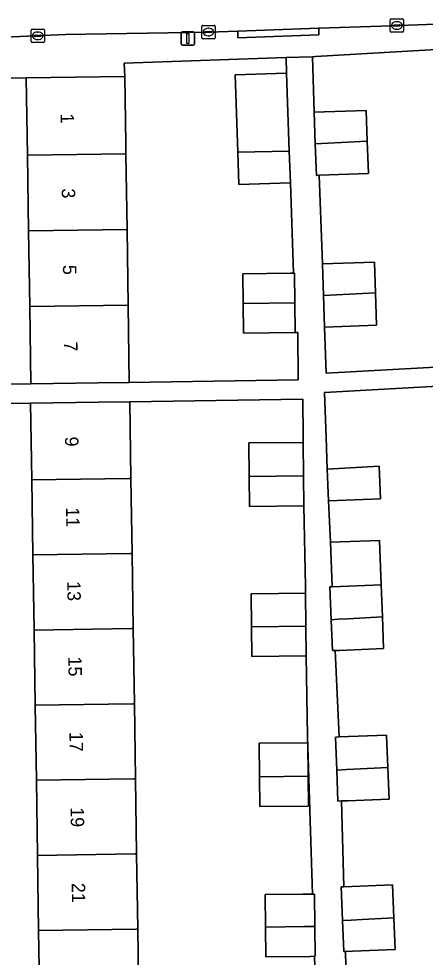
# Model space of a CAD drawing. Extents: x 162250 to 162661, y 380743 to 381606.
# Drawn here: x 162441.5 to 162471.8, y 380821.9 to 380891.8 of the extents above; entities that cross this region are included whole.
import ezdxf

# ---------------------------------------------------------------- set-up
doc = ezdxf.new("R2010")
doc.units = 0
for name, color, linetype in [('IMGEO_Erf', 7, 'Continuous'), ('IMGEO_Kolk', 7, 'Continuous'), ('IMGEO_Lichtmast', 7, 'Continuous'), ('IMGEO_Pand', 7, 'Continuous'), ('IMGEO_Pand_nummerreeks', 7, 'Continuous'), ('IMGEO_Rijbaan_lokaal_open', 7, 'Continuous'), ('IMGEO_Voetpad_open', 7, 'Continuous')]:
    doc.layers.add(name, color=color, linetype=linetype)

msp = doc.modelspace()

# ---------------------------------------------------------------- linework, layer by layer
at = {"layer": 'IMGEO_Erf'}
for points in [[(162476.003, 380877.506), (162472.856, 380877.338), (162472.553, 380882.993), (162475.699, 380883.161), (162475.657, 380883.948), (162475.388, 380888.933), (162475.802, 380888.955), (162475.764, 380889.728), (162473.498, 380889.596), (162463.611, 380889.016), (162463.383, 380889.008), (162463.524, 380884.867), (162467.402, 380885), (162467.48, 380882.72), (162467.564, 380880.294), (162463.905, 380880.169), (162464.132, 380873.557), (162468.01, 380873.69), (162468.088, 380871.41), (162468.172, 380868.984), (162464.294, 380868.851), (162464.412, 380865.42), (162476.618, 380866.074), (162476.307, 380871.851)], [(162461.746, 380879.605), (162457.906, 380879.474), (162457.823, 380881.899), (162457.625, 380887.664), (162461.465, 380887.795), (162461.426, 380888.942), (162449.36, 380888.532), (162449.389, 380887.538), (162449.464, 380882.539), (162449.476, 380881.775), (162449.561, 380876.13), (162449.646, 380870.485), (162449.733, 380864.72), (162462.337, 380864.908), (162462.299, 380868.444), (162462.101, 380868.442), (162458.254, 380868.4), (162458.229, 380870.613), (162458.205, 380872.83), (162461.752, 380872.868), (162461.964, 380872.87), (162461.978, 380872.87)], [(162442.218, 380876.02), (162442.133, 380881.666), (162442.046, 380887.428), (162438.964, 380887.383), (162439.295, 380864.563), (162442.391, 380864.609), (162442.304, 380870.375)], [(162442.881, 380829.455), (162442.797, 380835.055), (162442.713, 380840.656), (162442.628, 380846.255), (162442.544, 380851.855), (162442.459, 380857.455), (162442.373, 380863.173), (162439.316, 380863.127), (162440.296, 380795.687), (162443.39, 380795.737), (162443.304, 380801.456), (162443.219, 380807.055), (162443.135, 380812.655), (162443.05, 380818.255), (162442.966, 380823.855)], [(162459.436, 380835.302), (162459.409, 380837.815), (162463.038, 380837.854), (162463.065, 380835.356), (162463.089, 380833.126), (162459.46, 380833.087)]]:
    msp.add_lwpolyline(points, close=True, dxfattribs=at)
for points in [[(162472.756, 380864.438), (162464.301, 380863.978), (162464.417, 380860.611), (162464.498, 380858.256), (162468.373, 380858.466), (162468.457, 380856.038), (162464.579, 380855.905), (162464.737, 380852.801), (162468.382, 380852.945), (162468.513, 380849.631), (162468.608, 380847.235), (162468.701, 380844.872), (162465.411, 380844.742), (162465.083, 380844.729), (162465.373, 380838.29), (162468.924, 380838.429), (162469.02, 380836.014), (162469.114, 380833.653), (162466.011, 380833.531), (162465.558, 380833.513), (162465.722, 380827.109), (162469.367, 380827.253), (162469.465, 380824.795), (162469.558, 380822.433), (162466.372, 380822.308), (162465.846, 380822.287), (162465.931, 380818.981)], [(162463.736, 380815.915), (162463.547, 380821.928), (162463.257, 380821.925), (162459.919, 380821.889), (162459.894, 380824.104), (162459.866, 380826.533), (162462.686, 380826.564), (162463.207, 380826.57), (162463.401, 380826.572), (162463.033, 380838.307), (162462.921, 380844.325), (162458.876, 380844.281), (162458.851, 380846.494), (162458.824, 380848.961), (162462.87, 380849.005), (162462.865, 380849.506), (162462.753, 380855.526), (162458.708, 380855.482), (162458.683, 380857.695), (162458.656, 380860.207), (162462.702, 380860.251), (162462.697, 380860.707), (162462.667, 380863.477), (162449.771, 380863.284), (162449.857, 380857.565), (162449.942, 380851.965), (162450.026, 380846.364), (162450.111, 380840.765), (162450.195, 380835.165), (162450.28, 380829.564), (162450.364, 380823.964), (162450.448, 380818.365)]]:
    msp.add_lwpolyline(points, dxfattribs=at)
at = {"layer": 'IMGEO_Kolk'}
for p, q in [((162469.187, 380890.914), (162469.187, 380891.766)), ((162469.262, 380891.84), (162470.114, 380891.84)), ((162470.188, 380891.766), (162470.188, 380890.914)), ((162442.477, 380891.073), (162443.329, 380891.073)), ((162455.134, 380890.424), (162455.134, 380891.276)), ((162455.209, 380891.35), (162456.061, 380891.35)), ((162455.622, 380891.13), (162455.647, 380891.13)), ((162456.135, 380891.276), (162456.135, 380890.424)), ((162469.446, 380891.334), (162469.446, 380891.346)), ((162469.884, 380891.297), (162469.486, 380891.297)), ((162469.489, 380891.383), (162469.887, 380891.383)), ((162469.698, 380891.06), (162469.673, 380891.06)), ((162469.675, 380891.62), (162469.7, 380891.62)), ((162469.93, 380891.346), (162469.93, 380891.334)), ((162442.402, 380890.147), (162442.402, 380890.999)), ((162442.661, 380890.567), (162442.661, 380890.579)), ((162443.099, 380890.53), (162442.701, 380890.53)), ((162442.704, 380890.616), (162443.102, 380890.616)), ((162442.89, 380890.853), (162442.915, 380890.853)), ((162443.145, 380890.579), (162443.145, 380890.567)), ((162443.403, 380890.999), (162443.403, 380890.147)), ((162455.393, 380890.844), (162455.393, 380890.856)), ((162455.831, 380890.807), (162455.433, 380890.807)), ((162455.436, 380890.893), (162455.834, 380890.893)), ((162455.645, 380890.57), (162455.62, 380890.57)), ((162455.877, 380890.856), (162455.877, 380890.844)), ((162470.114, 380890.84), (162469.262, 380890.84)), ((162443.329, 380890.073), (162442.477, 380890.073)), ((162442.913, 380890.293), (162442.888, 380890.293)), ((162456.061, 380890.35), (162455.209, 380890.35))]:
    msp.add_line(p, q, dxfattribs=at)
for points in [[(162469.187, 380890.914), (162469.187, 380891.766)], [(162469.262, 380891.84), (162470.114, 380891.84)], [(162470.188, 380891.766), (162470.188, 380890.914)], [(162442.477, 380891.073), (162443.329, 380891.073)], [(162455.134, 380890.424), (162455.134, 380891.276)], [(162455.209, 380891.35), (162456.061, 380891.35)], [(162456.135, 380891.276), (162456.135, 380890.424)], [(162442.402, 380890.147), (162442.402, 380890.999)], [(162443.403, 380890.999), (162443.403, 380890.147)], [(162470.114, 380890.84), (162469.262, 380890.84)], [(162443.329, 380890.073), (162442.477, 380890.073)], [(162456.061, 380890.35), (162455.209, 380890.35)]]:
    msp.add_lwpolyline(points, dxfattribs=at)
for centre, radius, start, end in [((162469.264, 380891.764), 0.0765, 91.55205, 178.44795), ((162469.264, 380891.764), 0.0765, 91.55205, 178.44795), ((162470.112, 380891.764), 0.0765, 1.55205, 88.44795), ((162470.112, 380891.764), 0.0765, 1.55205, 88.44795), ((162442.479, 380890.997), 0.0765, 91.55205, 178.44795), ((162442.479, 380890.997), 0.0765, 91.55205, 178.44795), ((162443.327, 380890.997), 0.0765, 1.55205, 88.44795), ((162443.327, 380890.997), 0.0765, 1.55205, 88.44795), ((162455.211, 380891.274), 0.0765, 91.55205, 178.44795), ((162455.211, 380891.274), 0.0765, 91.55205, 178.44795), ((162456.059, 380891.274), 0.0765, 1.55205, 88.44795), ((162456.059, 380891.274), 0.0765, 1.55205, 88.44795), ((162469.486, 380891.343), 0.0403, 85.87752, 175.75265), ((162469.483, 380891.333), 0.0366, 178.93798, 274.71019), ((162469.887, 380891.34), 0.043, 264.86636, 352.45326), ((162469.891, 380891.345), 0.0386, 1.73085, 96.63898), ((162442.701, 380890.576), 0.0403, 85.87752, 175.75265), ((162442.698, 380890.566), 0.0366, 178.93798, 274.71019), ((162443.102, 380890.573), 0.043, 264.86636, 352.45326), ((162443.106, 380890.578), 0.0386, 1.73085, 96.63898), ((162455.211, 380890.426), 0.0765, 181.55205, 268.44795), ((162455.211, 380890.426), 0.0765, 181.55205, 268.44795), ((162455.433, 380890.853), 0.0403, 85.87752, 175.75265), ((162455.43, 380890.843), 0.0366, 178.93798, 274.71019), ((162455.834, 380890.85), 0.043, 264.86636, 352.45326), ((162455.838, 380890.855), 0.0386, 1.73085, 96.63898), ((162456.059, 380890.426), 0.0765, 271.55205, 358.44795), ((162456.059, 380890.426), 0.0765, 271.55205, 358.44795), ((162469.264, 380890.916), 0.0765, 181.55205, 268.44795), ((162469.264, 380890.916), 0.0765, 181.55205, 268.44795), ((162470.112, 380890.916), 0.0765, 271.55205, 358.44795), ((162470.112, 380890.916), 0.0765, 271.55205, 358.44795), ((162442.479, 380890.149), 0.0765, 181.55205, 268.44795), ((162442.479, 380890.149), 0.0765, 181.55205, 268.44795), ((162443.327, 380890.149), 0.0765, 271.55205, 358.44795), ((162443.327, 380890.149), 0.0765, 271.55205, 358.44795)]:
    msp.add_arc(centre, radius, start, end, dxfattribs=at)
for centre, major_axis, ratio, start_param, end_param in [((162455.621, 380890.85), (-0.387, 0.002), 0.722429, 4.712389, 7.853982), ((162455.646, 380890.85), (-0.39, 0.002), 0.717154, 1.570796, 4.712389), ((162469.674, 380891.34), (-0.387, 0.002), 0.722429, 4.712389, 7.853982), ((162469.699, 380891.34), (-0.39, 0.002), 0.717154, 1.570796, 4.712389), ((162442.889, 380890.573), (-0.387, 0.002), 0.722429, 4.712389, 7.853982), ((162442.914, 380890.573), (-0.39, 0.002), 0.717154, 1.570796, 4.712389)]:
    msp.add_ellipse(centre, major_axis=major_axis, ratio=ratio, start_param=start_param, end_param=end_param, dxfattribs=at)
at = {"layer": 'IMGEO_Lichtmast'}
for p, q in [((162453.599, 380889.967), (162453.599, 380890.767)), ((162453.599, 380890.767), (162453.599, 380889.967)), ((162453.699, 380890.867), (162454.489, 380890.867)), ((162454.489, 380890.867), (162453.699, 380890.867)), ((162454.589, 380890.767), (162454.589, 380889.967)), ((162454.589, 380889.967), (162454.589, 380890.767)), ((162454.489, 380889.867), (162453.699, 380889.867)), ((162453.699, 380889.867), (162454.489, 380889.867))]:
    msp.add_line(p, q, dxfattribs=at)
msp.add_lwpolyline([(162454.019, 380890.742), (162454.169, 380890.742), (162454.169, 380889.992), (162454.019, 380889.992), (162454.019, 380890.742)], dxfattribs=at)
for centre, start, end in [((162453.699, 380890.767), 90, 180), ((162453.699, 380890.767), 90, 180), ((162454.489, 380890.767), 0, 90), ((162454.489, 380890.767), 360, 90), ((162453.699, 380889.967), 180, 270), ((162453.699, 380889.967), 180, 270), ((162454.489, 380889.967), 270, 0), ((162454.489, 380889.967), 270, 0)]:
    msp.add_arc(centre, 0.1, start, end, dxfattribs=at)
at = {"layer": 'IMGEO_Pand'}
for points in [[(162457.823, 380881.899), (162461.665, 380881.956), (162461.465, 380887.795), (162457.625, 380887.664)], [(162442.133, 380881.666), (162449.476, 380881.775), (162449.464, 380882.539), (162449.389, 380887.538), (162442.046, 380887.428)], [(162467.48, 380882.72), (162467.402, 380885), (162463.524, 380884.867), (162463.605, 380882.512)], [(162467.48, 380882.72), (162463.605, 380882.512), (162463.686, 380880.161), (162463.905, 380880.169), (162467.564, 380880.294)], [(162457.823, 380881.899), (162457.906, 380879.474), (162461.746, 380879.605), (162461.665, 380881.956)], [(162442.133, 380881.666), (162442.218, 380876.02), (162449.561, 380876.13), (162449.476, 380881.775)], [(162449.646, 380870.485), (162449.561, 380876.13), (162442.218, 380876.02), (162442.304, 380870.375)], [(162464.213, 380871.202), (162468.088, 380871.41), (162468.01, 380873.69), (162464.132, 380873.557)], [(162461.978, 380872.87), (162461.964, 380872.87), (162461.752, 380872.868), (162458.205, 380872.83), (162458.229, 380870.613), (162462.077, 380870.67), (162462.053, 380872.871)], [(162464.213, 380871.202), (162464.294, 380868.851), (162468.172, 380868.984), (162468.088, 380871.41)], [(162449.646, 380870.485), (162442.304, 380870.375), (162442.391, 380864.609), (162447.391, 380864.685), (162449.733, 380864.72)], [(162462.077, 380870.67), (162458.229, 380870.613), (162458.254, 380868.4), (162462.101, 380868.442)], [(162449.857, 380857.565), (162449.771, 380863.284), (162447.435, 380863.249), (162442.373, 380863.173), (162442.459, 380857.455), (162449.733, 380857.563)], [(162462.702, 380860.251), (162458.656, 380860.207), (162458.683, 380857.695), (162462.729, 380857.755)], [(162468.373, 380858.466), (162464.498, 380858.256), (162464.579, 380855.905), (162468.457, 380856.038)], [(162449.857, 380857.565), (162449.733, 380857.563), (162442.459, 380857.455), (162442.544, 380851.855), (162449.817, 380851.963), (162449.942, 380851.965)], [(162462.729, 380857.755), (162458.683, 380857.695), (162458.708, 380855.482), (162462.753, 380855.526)], [(162464.737, 380852.801), (162464.868, 380849.487), (162468.513, 380849.631), (162468.382, 380852.945)], [(162450.026, 380846.364), (162449.942, 380851.965), (162449.817, 380851.963), (162442.544, 380851.855), (162442.628, 380846.255), (162449.901, 380846.362)], [(162464.868, 380849.487), (162464.692, 380849.48), (162464.789, 380847.028), (162465.319, 380847.057), (162466.029, 380847.095), (162468.608, 380847.235), (162468.513, 380849.631)], [(162462.87, 380849.005), (162458.824, 380848.961), (162458.851, 380846.494), (162462.897, 380846.553)], [(162468.608, 380847.235), (162466.029, 380847.095), (162465.319, 380847.057), (162464.789, 380847.028), (162464.881, 380844.721), (162465.083, 380844.729), (162465.411, 380844.742), (162468.701, 380844.872)], [(162450.026, 380846.364), (162449.901, 380846.362), (162442.628, 380846.255), (162442.713, 380840.656), (162449.985, 380840.763), (162450.111, 380840.765)], [(162458.851, 380846.494), (162458.876, 380844.281), (162462.921, 380844.325), (162462.897, 380846.553)], [(162442.797, 380835.055), (162450.069, 380835.163), (162450.195, 380835.165), (162450.111, 380840.765), (162449.985, 380840.763), (162442.713, 380840.656)], [(162465.373, 380838.29), (162465.1, 380838.279), (162465.198, 380835.807), (162465.919, 380835.846), (162466.453, 380835.875), (162469.02, 380836.014), (162468.924, 380838.429)], [(162459.436, 380835.302), (162463.065, 380835.356), (162463.038, 380837.854), (162459.409, 380837.815)], [(162469.02, 380836.014), (162466.453, 380835.875), (162465.919, 380835.846), (162465.198, 380835.807), (162465.29, 380833.503), (162465.558, 380833.513), (162466.011, 380833.531), (162469.114, 380833.653)], [(162442.881, 380829.455), (162450.153, 380829.562), (162450.28, 380829.564), (162450.195, 380835.165), (162450.069, 380835.163), (162442.797, 380835.055)], [(162463.065, 380835.356), (162459.436, 380835.302), (162459.46, 380833.087), (162463.089, 380833.126)], [(162450.364, 380823.964), (162450.28, 380829.564), (162450.153, 380829.562), (162442.881, 380829.455), (162442.966, 380823.855), (162450.237, 380823.962)], [(162465.722, 380827.109), (162465.544, 380827.102), (162465.644, 380824.589), (162466.28, 380824.623), (162467.093, 380824.667), (162469.465, 380824.795), (162469.367, 380827.253)], [(162463.401, 380826.572), (162463.207, 380826.57), (162462.686, 380826.564), (162459.866, 380826.533), (162459.894, 380824.104), (162462.793, 380824.147), (162463.233, 380824.153), (162463.571, 380824.158), (162463.545, 380826.573)], [(162469.465, 380824.795), (162467.093, 380824.667), (162466.28, 380824.623), (162465.644, 380824.589), (162465.736, 380822.283), (162465.846, 380822.287), (162466.372, 380822.308), (162469.558, 380822.433)], [(162450.364, 380823.964), (162450.237, 380823.962), (162442.966, 380823.855), (162443.05, 380818.255), (162450.321, 380818.363), (162450.448, 380818.365)], [(162463.571, 380824.158), (162463.233, 380824.153), (162462.793, 380824.147), (162459.894, 380824.104), (162459.919, 380821.889), (162463.257, 380821.925), (162463.547, 380821.928), (162463.595, 380821.929)]]:
    msp.add_lwpolyline(points, close=True, dxfattribs=at)
at = {"layer": 'IMGEO_Rijbaan_lokaal_open'}
msp.add_lwpolyline([(162439.842, 380890.44), (162444.978, 380890.665), (162455.661, 380890.851), (162457.816, 380890.926), (162463.857, 380891.137), (162468.515, 380891.299), (162483.523, 380891.833)], dxfattribs=at)
at = {"layer": 'IMGEO_Voetpad_open'}
for points in [[(162483.523, 380891.833), (162468.515, 380891.299), (162463.857, 380891.137), (162463.872, 380890.638), (162457.831, 380890.427), (162457.816, 380890.926), (162455.661, 380890.851), (162444.978, 380890.665), (162439.842, 380890.44)], [(162436.137, 380887.782), (162436.094, 380887.375), (162438.964, 380887.383), (162442.046, 380887.428), (162449.389, 380887.538), (162449.36, 380888.532), (162461.426, 380888.942), (162463.383, 380889.008), (162463.611, 380889.016), (162473.498, 380889.596), (162475.764, 380889.728), (162475.802, 380888.955), (162482.75, 380889.328), (162484.236, 380889.431), (162487.87, 380889.579)], [(162476.618, 380866.074), (162464.412, 380865.42), (162464.294, 380868.851), (162464.213, 380871.202), (162464.132, 380873.557), (162463.905, 380880.169), (162463.686, 380880.161), (162463.605, 380882.512), (162463.524, 380884.867), (162463.383, 380889.008), (162461.426, 380888.942), (162461.465, 380887.795), (162461.665, 380881.956), (162461.746, 380879.605), (162461.978, 380872.87), (162462.053, 380872.871), (162462.077, 380870.67), (162462.101, 380868.442), (162462.299, 380868.444), (162462.337, 380864.908), (162449.733, 380864.72), (162447.391, 380864.685), (162442.391, 380864.609), (162439.295, 380864.563)], [(162465.931, 380818.981), (162465.846, 380822.287), (162465.736, 380822.283), (162465.644, 380824.589), (162465.544, 380827.102), (162465.722, 380827.109), (162465.558, 380833.513), (162465.29, 380833.503), (162465.198, 380835.807), (162465.1, 380838.279), (162465.373, 380838.29), (162465.083, 380844.729), (162464.881, 380844.721), (162464.789, 380847.028), (162464.692, 380849.48), (162464.868, 380849.487), (162464.737, 380852.801), (162464.579, 380855.905), (162464.498, 380858.256), (162464.417, 380860.611), (162464.301, 380863.978), (162472.756, 380864.438)], [(162439.316, 380863.127), (162442.373, 380863.173), (162447.435, 380863.249), (162449.771, 380863.284), (162462.667, 380863.477), (162462.697, 380860.707), (162462.702, 380860.251), (162462.729, 380857.755), (162462.753, 380855.526), (162462.865, 380849.506), (162462.87, 380849.005), (162462.897, 380846.553), (162462.921, 380844.325), (162463.033, 380838.307), (162463.401, 380826.572), (162463.545, 380826.573), (162463.571, 380824.158), (162463.595, 380821.929), (162463.547, 380821.928), (162463.736, 380815.915)]]:
    msp.add_lwpolyline(points, dxfattribs=at)
msp.add_lwpolyline([(162457.816, 380890.926), (162457.831, 380890.427), (162463.872, 380890.638), (162463.857, 380891.137)], close=True, dxfattribs=at)

# ---------------------------------------------------------------- texts
at = {"layer": 'IMGEO_Pand_nummerreeks'}
for s, rotation, p in [('1', 270.86619, (162444.607, 380884.775)), ('3', 270.86619, (162444.691, 380879.185)), ('5', 270.86619, (162444.777, 380873.48)), ('7', 270.86619, (162444.864, 380867.775)), ('9', 270.86401, (162444.931, 380860.677)), ('11', 270.86401, (162445.01, 380855.403)), ('13', 270.86401, (162445.094, 380849.898)), ('15', 270.86401, (162445.178, 380844.278)), ('17', 270.86401, (162445.263, 380838.658)), ('19', 270.86401, (162445.348, 380833.039)), ('21', 270.86401, (162445.433, 380827.397))]:
    msp.add_text(s, height=1, rotation=rotation, dxfattribs=at).set_placement(p)

doc.saveas('drawing.dxf')
